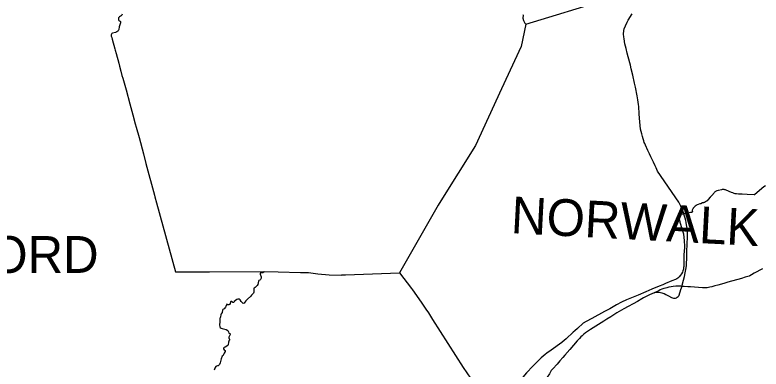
# Model space of a CAD drawing. Extents: x 0 to 2603, y -226 to 830.
# Drawn here: x 49.3 to 76.71, y 483.67 to 496.67 of the extents above; entities that cross this region are included whole.
import ezdxf

# ---------------------------------------------------------------- set-up
doc = ezdxf.new("R2010")
doc.units = 0
for name, color, linetype in [('CT_TSH_Map_Interstate_Roads', 7, 'Continuous'), ('CT_TSH_Map_Town_Limits', 7, 'Continuous'), ('CT_TSH_Map_Town_Text', 7, 'Continuous'), ('CT_TSH_Map_US_and_State_Routes', 7, 'Continuous')]:
    doc.layers.add(name, color=color, linetype=linetype)

msp = doc.modelspace()

# ---------------------------------------------------------------- linework, layer by layer
at = {"layer": 'CT_TSH_Map_Interstate_Roads'}
for points in [[(76.762, 487.35), (76.457, 487.188), (76.357, 487.132), (76.288, 487.096), (76.277, 487.093)], [(76.277, 487.093), (76.268, 487.086), (76.127, 487.042), (75.982, 486.999), (75.85, 486.962)], [(75.343, 486.82), (75.114, 486.756), (75.001, 486.725), (74.897, 486.695)], [(75.485, 486.86), (75.343, 486.82)], [(75.617, 486.897), (75.485, 486.86)], [(75.85, 486.962), (75.617, 486.897)], [(73.241, 486.659), (73.199, 486.647), (73.133, 486.626), (73.059, 486.6), (73.004, 486.576), (72.945, 486.55), (72.887, 486.525), (72.782, 486.476)], [(73.399, 486.693), (73.316, 486.677), (73.241, 486.659)], [(73.479, 486.704), (73.399, 486.693)], [(73.722, 486.713), (73.662, 486.715), (73.578, 486.712), (73.479, 486.704)], [(73.791, 486.708), (73.754, 486.712), (73.722, 486.713)], [(73.883, 486.703), (73.824, 486.707), (73.791, 486.708)], [(74.112, 486.688), (74.015, 486.694), (73.883, 486.703)], [(74.556, 486.659), (74.112, 486.688)], [(74.631, 486.655), (74.556, 486.659)], [(74.897, 486.695), (74.822, 486.675), (74.774, 486.666), (74.731, 486.66), (74.675, 486.655), (74.631, 486.655)], [(72.329, 486.249), (72.161, 486.158)], [(72.392, 486.282), (72.329, 486.249)], [(72.782, 486.476), (72.607, 486.392), (72.392, 486.282)], [(72.004, 486.073), (71.819, 485.972), (71.669, 485.887), (71.409, 485.737)], [(72.161, 486.158), (72.004, 486.073)], [(71.409, 485.737), (71.182, 485.593)], [(70.927, 485.43), (70.444, 485.125), (70.363, 485.073), (70.26, 485)], [(71.182, 485.593), (71.04, 485.503), (70.927, 485.43)], [(70.26, 485), (70.195, 484.949), (70.13, 484.893), (70.086, 484.853), (70.034, 484.801), (69.949, 484.709), (69.815, 484.553), (69.675, 484.394)], [(69.675, 484.394), (69.497, 484.188), (69.42, 484.1), (69.31, 483.974), (69.212, 483.859)], [(69.212, 483.859), (69.057, 483.681), (69.001, 483.616), (68.93, 483.498), (68.849, 483.381), (68.795, 483.311), (68.741, 483.248), (68.672, 483.174), (68.6, 483.105)]]:
    msp.add_lwpolyline(points, dxfattribs=at)
at = {"layer": 'CT_TSH_Map_Town_Limits'}
for points in [[(68.064, 496.328), (71.04, 497.256), (72.281, 497.643), (73.048, 497.886), (73.368, 497.985), (74.898, 498.896), (77.077, 500.186), (77.62, 500.504), (78.048, 500.413), (78.726, 500.256), (79.046, 500.192)], [(53.236, 496.697), (53.228, 496.665), (53.204, 496.64), (53.175, 496.632), (53.14, 496.607), (53.105, 496.568), (53.098, 496.534), (53.099, 496.506), (53.114, 496.473), (53.133, 496.457), (53.168, 496.445), (53.178, 496.429), (53.177, 496.386), (53.13, 496.233), (53.116, 496.143), (53.092, 496.093), (53.082, 496.077), (53.043, 496.048), (52.989, 496.024), (52.887, 496.008), (52.857, 495.991), (52.836, 495.948), (52.838, 495.892), (52.853, 495.845), (52.868, 495.777), (52.965, 495.433), (52.979, 495.379), (53.011, 495.253), (53.115, 494.904), (53.137, 494.787), (53.189, 494.612), (53.231, 494.452), (53.263, 494.353), (53.382, 493.923), (53.52, 493.41), (53.635, 493.01), (53.717, 492.675), (53.753, 492.55), (53.857, 492.178), (54.018, 491.579), (54.11, 491.218), (54.426, 490.057), (54.443, 489.996), (54.493, 489.775), (55.199, 487.245), (56.059, 487.244), (56.122, 487.244), (56.445, 487.247), (58.453, 487.249)], [(67.957, 496.691), (67.961, 496.665), (67.959, 496.559), (67.98, 496.466), (68.024, 496.373), (68.064, 496.328)], [(68.064, 496.328), (67.895, 495.508), (67.177, 493.962), (66.215, 491.877), (64.942, 489.844), (64.849, 489.685), (63.427, 487.211)], [(58.453, 487.249), (58.438, 487.226), (58.405, 487.208), (58.339, 487.202), (58.311, 487.192), (58.302, 487.177), (58.302, 487.16), (58.346, 487.061), (58.345, 487.01), (58.334, 486.98), (58.315, 486.956), (58.288, 486.934), (58.263, 486.921), (58.243, 486.895), (58.222, 486.777), (58.199, 486.735), (58.117, 486.671), (58.089, 486.642), (58.078, 486.632), (58.07, 486.594), (58.069, 486.516), (58.071, 486.49), (58.061, 486.458), (58.039, 486.431), (57.991, 486.388), (57.958, 486.355), (57.835, 486.242), (57.78, 486.181), (57.742, 486.131), (57.713, 486.09), (57.686, 486.085), (57.658, 486.102), (57.612, 486.148), (57.574, 486.211), (57.551, 486.233), (57.523, 486.244), (57.482, 486.244), (57.444, 486.232), (57.396, 486.195), (57.357, 486.152), (57.348, 486.139), (57.321, 486.122), (57.299, 486.121), (57.253, 486.149), (57.23, 486.149), (57.221, 486.144), (57.206, 486.077), (57.184, 486.048), (57.155, 486.031), (57.135, 486.033), (57.119, 486.029), (57.101, 486.048), (57.085, 486.05), (57.072, 486.037), (57.05, 485.965), (57.037, 485.94), (56.98, 485.886), (56.954, 485.872), (56.935, 485.856), (56.923, 485.831), (56.905, 485.75), (56.876, 485.695), (56.861, 485.669), (56.848, 485.587), (56.834, 485.559), (56.826, 485.526), (56.821, 485.411), (56.812, 485.302), (56.824, 485.228), (56.843, 485.194), (56.877, 485.171), (56.914, 485.158), (56.955, 485.152), (57.058, 485.126), (57.114, 485.084), (57.138, 485.039), (57.152, 484.997), (57.167, 484.987), (57.196, 484.979), (57.207, 484.962), (57.205, 484.936), (57.159, 484.85), (57.158, 484.818), (57.183, 484.764), (57.182, 484.729), (57.161, 484.707), (57.154, 484.703), (57.141, 484.664), (57.134, 484.563), (57.122, 484.542), (57.022, 484.482), (56.983, 484.464), (56.959, 484.44), (56.961, 484.413), (56.982, 484.381), (57.018, 484.353), (57.022, 484.322), (56.979, 484.254), (56.965, 484.208), (56.943, 484.172), (56.916, 484.143)], [(58.453, 487.249), (58.962, 487.243), (59.786, 487.221), (60.085, 487.215), (60.426, 487.165), (60.835, 487.137), (61.277, 487.126), (61.31, 487.13), (61.44, 487.138), (63.427, 487.211)], [(63.427, 487.211), (63.87, 486.627), (63.903, 486.586), (64.221, 486.123), (64.396, 485.875), (64.486, 485.736), (64.639, 485.493), (65.768, 483.736), (66.033, 483.335)], [(56.916, 484.143), (56.874, 484.049), (56.864, 483.998), (56.832, 483.898), (56.807, 483.839), (56.79, 483.814), (56.762, 483.794), (56.741, 483.787), (56.697, 483.784), (56.675, 483.768), (56.64, 483.703), (56.619, 483.632)]]:
    msp.add_lwpolyline(points, dxfattribs=at)
at = {"layer": 'CT_TSH_Map_US_and_State_Routes'}
for points in [[(71.669, 496.102), (71.68, 496.161), (71.725, 496.269), (71.783, 496.408), (71.82, 496.48), (71.972, 496.707)], [(71.751, 495.436), (71.698, 495.608), (71.672, 495.791), (71.664, 495.864), (71.656, 495.965), (71.669, 496.102)], [(71.791, 495.272), (71.751, 495.436)], [(71.888, 494.91), (71.791, 495.272)], [(71.911, 494.834), (71.888, 494.91)], [(71.939, 494.699), (71.911, 494.834)], [(72.096, 494.016), (72.057, 494.166), (71.992, 494.463), (71.939, 494.699)], [(72.157, 493.697), (72.096, 494.016)], [(72.183, 493.554), (72.157, 493.697)], [(72.207, 493.379), (72.183, 493.554)], [(72.266, 492.618), (72.252, 492.75), (72.238, 492.885), (72.222, 493.036), (72.215, 493.309), (72.207, 493.379)], [(72.28, 492.478), (72.266, 492.618)], [(72.417, 491.994), (72.404, 492.052), (72.375, 492.129), (72.348, 492.21), (72.324, 492.307), (72.28, 492.478)], [(72.462, 491.887), (72.433, 491.95), (72.417, 491.994)], [(72.76, 491.266), (72.659, 491.469), (72.61, 491.569), (72.546, 491.702), (72.462, 491.887)], [(72.815, 491.129), (72.76, 491.266)], [(72.906, 490.934), (72.855, 491.06), (72.815, 491.129)], [(73.684, 489.803), (72.906, 490.934)], [(76.867, 490.403), (76.813, 490.359), (76.476, 490.075), (76.466, 490.072), (76.449, 490.072), (76.191, 490.084)], [(74.99, 490.159), (74.894, 490.047), (74.838, 489.982), (74.761, 489.892), (74.724, 489.854), (74.697, 489.832), (74.659, 489.809)], [(75.136, 490.227), (75.135, 490.226), (75.079, 490.211), (75.061, 490.205), (75.051, 490.201), (75.026, 490.188), (75.006, 490.174), (74.99, 490.159)], [(75.248, 490.257), (75.136, 490.227)], [(75.347, 490.262), (75.327, 490.265), (75.305, 490.265), (75.28, 490.263), (75.248, 490.257)], [(75.614, 490.158), (75.535, 490.192), (75.404, 490.247), (75.386, 490.253), (75.369, 490.258), (75.347, 490.262)], [(75.873, 490.098), (75.806, 490.1), (75.786, 490.102), (75.755, 490.107), (75.722, 490.116), (75.691, 490.126), (75.663, 490.138), (75.614, 490.158)], [(76.013, 490.092), (75.969, 490.094), (75.873, 490.098)], [(76.191, 490.084), (76.013, 490.092)], [(73.759, 489.652), (73.684, 489.803)], [(74.659, 489.809), (74.624, 489.793), (74.6, 489.783), (74.594, 489.781), (74.56, 489.77)], [(73.872, 489.369), (73.834, 489.479), (73.759, 489.652)], [(74.355, 489.699), (74.338, 489.69), (74.319, 489.678), (74.284, 489.652), (74.244, 489.615), (74.217, 489.58), (74.195, 489.544), (74.185, 489.525), (74.178, 489.508), (74.176, 489.501), (74.174, 489.483), (74.175, 489.472), (74.177, 489.462), (74.178, 489.46), (74.18, 489.458), (74.182, 489.453), (74.183, 489.449), (74.182, 489.441)], [(74.396, 489.716), (74.355, 489.699)], [(74.56, 489.77), (74.487, 489.744), (74.456, 489.734), (74.396, 489.716)], [(73.828, 489.36), (73.679, 489.331)], [(73.679, 489.331), (73.68, 489.324), (73.682, 489.308), (73.687, 489.278), (73.714, 489.125)], [(73.872, 489.369), (73.828, 489.36)], [(74.003, 489.395), (73.872, 489.369)], [(73.997, 488.687), (73.985, 488.847), (73.978, 488.911), (73.97, 488.965), (73.954, 489.05), (73.939, 489.129), (73.919, 489.209), (73.897, 489.288), (73.872, 489.369)], [(74.182, 489.441), (74.18, 489.436), (74.168, 489.427), (74.158, 489.425), (74.111, 489.416), (74.003, 489.395)], [(73.714, 489.125), (73.72, 489.092)], [(73.72, 489.092), (73.723, 489.078)], [(73.723, 489.078), (73.724, 489.071), (73.859, 488.634)], [(73.997, 488.615), (73.997, 488.687)], [(73.859, 488.634), (73.88, 488.381), (73.898, 488.18), (73.895, 488.153), (73.88, 487.984), (73.87, 487.877)], [(73.977, 487.869), (73.983, 488.047), (73.988, 488.2), (73.992, 488.302), (73.999, 488.476), (73.997, 488.615)], [(73.87, 487.877), (73.866, 487.707), (73.866, 487.443)], [(73.963, 487.47), (73.971, 487.576), (73.974, 487.711), (73.977, 487.869)], [(73.866, 487.443), (73.862, 487.4), (73.853, 487.339), (73.836, 487.281), (73.814, 487.225), (73.785, 487.171), (73.748, 487.114), (73.7, 487.058), (73.651, 487.013), (73.608, 486.981), (73.562, 486.96)], [(73.92, 487.206), (73.953, 487.394)], [(73.953, 487.394), (73.963, 487.47)], [(73.78, 486.658), (73.852, 486.942), (73.89, 487.067), (73.92, 487.206)], [(73.192, 486.81), (73.094, 486.769), (72.962, 486.713), (72.696, 486.602)], [(73.432, 486.908), (73.192, 486.81)], [(73.562, 486.96), (73.432, 486.908)], [(72.47, 486.508), (72.187, 486.39)], [(72.696, 486.602), (72.47, 486.508)], [(72.782, 486.476), (72.814, 486.49), (72.861, 486.496), (72.916, 486.499), (72.964, 486.495), (73.015, 486.486), (73.058, 486.474), (73.101, 486.461), (73.143, 486.442), (73.204, 486.409)], [(73.204, 486.409), (73.311, 486.358), (73.417, 486.304), (73.454, 486.287), (73.492, 486.279), (73.526, 486.277), (73.564, 486.281), (73.6, 486.292), (73.629, 486.307), (73.666, 486.336), (73.687, 486.359), (73.697, 486.375), (73.701, 486.387), (73.764, 486.589)], [(73.764, 486.589), (73.78, 486.658)], [(71.94, 486.285), (71.758, 486.21), (71.579, 486.129), (71.393, 486.029)], [(72.128, 486.365), (71.94, 486.285)], [(72.187, 486.39), (72.128, 486.365)], [(71.393, 486.029), (71.271, 485.954), (71.151, 485.888)], [(70.96, 485.785), (70.487, 485.529), (70.281, 485.417), (70.167, 485.356)], [(71.151, 485.888), (70.96, 485.785)], [(70.167, 485.356), (69.959, 485.164), (69.86, 485.076)], [(69.809, 485.031), (69.541, 484.785), (69.468, 484.72), (69.395, 484.662), (69.383, 484.653), (68.993, 484.369)], [(69.86, 485.076), (69.809, 485.031)], [(68.993, 484.369), (68.837, 484.255), (68.772, 484.202), (68.702, 484.142), (68.633, 484.081), (68.499, 483.952), (68.319, 483.774)], [(68.319, 483.774), (68.095, 483.53), (68.02, 483.444), (67.935, 483.339), (67.9, 483.298), (67.869, 483.258), (67.756, 483.132)]]:
    msp.add_lwpolyline(points, dxfattribs=at)

# ---------------------------------------------------------------- texts
at = {"layer": 'CT_TSH_Map_Town_Text'}
for s, rotation, p in [('NORWALK', 357.0008, (67.497, 488.663)), ('STAMFORD', 360, (42.243, 487.204))]:
    msp.add_text(s, height=1.35, rotation=rotation, dxfattribs=at).set_placement(p)

doc.saveas('drawing.dxf')
